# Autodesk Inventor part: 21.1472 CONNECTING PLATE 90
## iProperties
Created: 2007-01
Part Number: 21.1472 CONNECTING PLATE 90
Document SubType Name: Modeling
Designer: Andy Moles
Material: Aluminum-6061
Description: DRILL & TAP M6 4 PLCS
Mass: 306.083 g
Surface Area: 236.474 cm^2
Volume: 112.946 cm^3
Density: 2.71 g/cm^3
Author: Andy Moles
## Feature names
1. Extrusion1
2. Hole1
3. Hole2
4. Fillet1
5. Hole3
6. Hole4
7. Extrusion2
